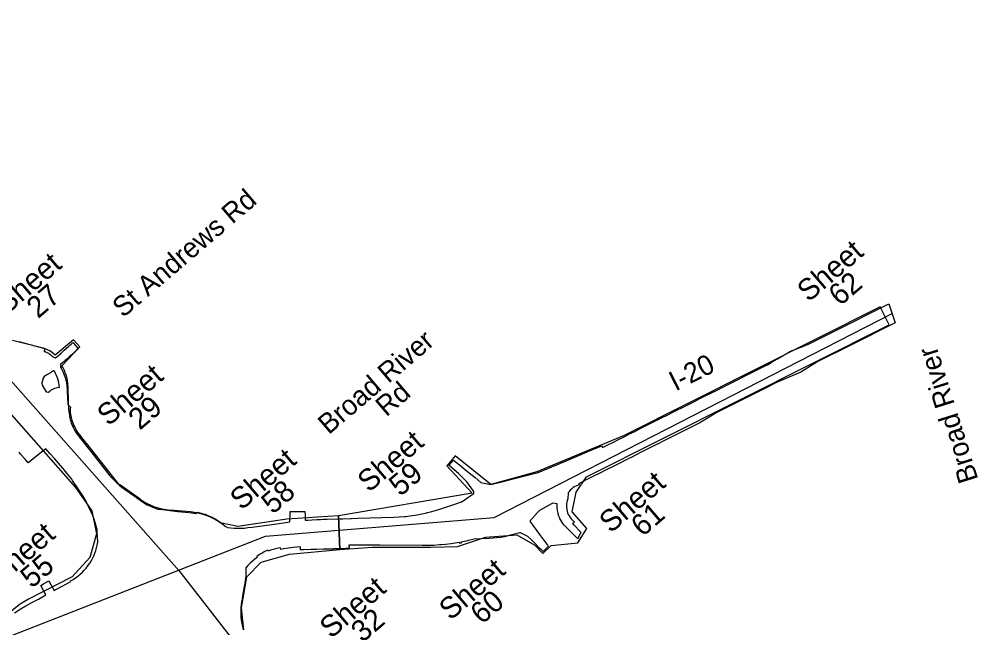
# Model space of a CAD drawing. Extents: x 1944182 to 1978751, y 789830 to 827717.
# Drawn here: x 1964336 to 1978751, y 800860 to 810005 of the extents above; entities that cross this region are included whole.
import ezdxf

# ---------------------------------------------------------------- set-up
doc = ezdxf.new("R2010")
doc.units = 0
for name, color, linetype in [('Default', 7, 'Continuous'), ('RD_AR_02', 7, 'Continuous'), ('RD_AR_03', 7, 'Continuous'), ('RD_SHT_ID', 7, 'Continuous'), ('RD_SHT_Misc4', 7, 'Continuous')]:
    doc.layers.add(name, color=color, linetype=linetype)

msp = doc.modelspace()

# ---------------------------------------------------------------- linework, layer by layer
at = {"layer": 'Default'}
for points in [[(1964332, 805162), (1964626, 805081), (1964700, 805061), (1964722, 805054), (1964721, 805051), (1964709, 805016), (1964709, 805016), (1964714, 805014), (1964716, 805014), (1964722, 805012), (1964724, 805011), (1964741, 805003), (1964749, 805000), (1964751, 804999), (1964766, 804991), (1964776, 804985), (1964788, 804978), (1964790, 804976), (1964799, 804970), (1964812, 804960), (1964821, 804953), (1964824, 804950), (1964833, 804942), (1964845, 804931), (1964880, 804914), (1964908, 804937), (1964920, 804948), (1964936, 804961), (1964966, 804989), (1965004, 805023), (1965012, 805030), (1965012, 805030), (1965077, 805089), (1965092, 805102), (1965117, 805124), (1965144, 805148), (1965151, 805139), (1965205, 805077), (1965205, 805077), (1965225, 805053), (1965200, 805030), (1965176, 805010), (1965175, 805009), (1965119, 804958), (1965093, 804935), (1965057, 804902), (1965026, 804874), (1965020, 804869), (1965013, 804863), (1965013, 804863), (1964989, 804842), (1964958, 804816), (1964958, 804813), (1964958, 804795), (1964958, 804778), (1964972, 804752), (1964978, 804740), (1964996, 804701), (1965002, 804687), (1965002, 804686), (1965012, 804661), (1965014, 804657), (1965014, 804655), (1965026, 804620), (1965031, 804600), (1965037, 804579), (1965040, 804565), (1965045, 804542), (1965045, 804537), (1965052, 804495), (1965052, 804488), (1965055, 804452), (1965057, 804416), (1965057, 804413), (1965069, 804227), (1965070, 804209), (1965105, 804177), (1965104, 804152), (1965103, 804105), (1965108, 804063), (1965117, 804022), (1965128, 803981), (1965141, 803941), (1965157, 803902), (1965166, 803885), (1965176, 803864), (1965196, 803827), (1965219, 803792), (1965244, 803758), (1965330, 803648), (1965343, 803632), (1965547, 803373), (1965843, 802998), (1965934, 802933), (1966065, 802842), (1966177, 802762), (1966259, 802710), (1966299, 802691), (1966340, 802673), (1966343, 802672), (1966382, 802658), (1966423, 802645), (1966450, 802641), (1966602, 802624), (1966721, 802610), (1966886, 802591), (1966931, 802585), (1966961, 802581), (1966992, 802576), (1967020, 802598), (1967088, 802578), (1967130, 802565), (1967172, 802549), (1967213, 802532), (1967252, 802512), (1967291, 802491), (1967329, 802467), (1967365, 802442), (1967400, 802415), (1967434, 802387), (1967468, 802367), (1967519, 802361), (1967570, 802357), (1967621, 802355), (1967672, 802356), (1967724, 802359), (1967775, 802365), (1967837, 802373), (1968211, 802424), (1968373, 802446), (1968408, 802450), (1968408, 802451), (1968410, 802561), (1968411, 802608), (1968633, 802610), (1968634, 802563), (1968634, 802562), (1968635, 802475), (1968683, 802478), (1968742, 802482), (1968819, 802487), (1968868, 802489), (1968909, 802490), (1968968, 802492), (1969154, 802498), (1969204, 802499), (1969330, 802503), (1969333, 802503), (1969429, 802506), (1969971, 802522), (1970050, 802525), (1970130, 802532), (1970149, 802534), (1970209, 802541), (1970288, 802552), (1970341, 802562), (1970342, 802562), (1970366, 802566), (1970444, 802583), (1970476, 802591), (1970522, 802602), (1970598, 802624), (1970674, 802648), (1970675, 802648), (1970888, 802720), (1970986, 802753), (1971026, 802779), (1971081, 802817), (1971083, 802818), (1971170, 802880), (1971172, 802907), (1971066, 803052), (1971022, 803096), (1970941, 803176), (1970877, 803233), (1970798, 803302), (1970805, 803310), (1970859, 803371), (1970868, 803381), (1970956, 803308), (1971057, 803225), (1971191, 803116), (1971279, 803043), (1971426, 803011), (1971591, 803054), (1971764, 803099), (1971785, 803104), (1972120, 803190), (1972141, 803196), (1972428, 803315), (1972724, 803439), (1972750, 803450), (1972840, 803487), (1972924, 803522), (1973012, 803559), (1973095, 803594), (1973109, 803570), (1973189, 803610), (1973270, 803651), (1973350, 803691), (1973431, 803731), (1973511, 803772), (1973592, 803812), (1973673, 803853), (1973753, 803893), (1973834, 803933), (1973914, 803974), (1973995, 804014), (1974088, 804061), (1974204, 804119), (1974328, 804181), (1974408, 804222), (1974489, 804262), (1974569, 804303), (1974650, 804343), (1974735, 804386), (1974829, 804433), (1974924, 804480), (1975035, 804536), (1975136, 804587), (1975251, 804645), (1975332, 804685), (1975412, 804725), (1975493, 804766), (1975581, 804810), (1975587, 804813), (1975659, 804855), (1975737, 804901), (1975835, 804957), (1975871, 804978), (1975934, 805015), (1976013, 805047), (1976118, 805089), (1976213, 805127), (1976576, 805309), (1977414, 805730), (1977507, 805441), (1977297, 805335), (1977061, 805217), (1976812, 805092), (1976347, 804859), (1976195, 804766), (1976091, 804702), (1975722, 804545), (1975566, 804467), (1974935, 804150), (1974935, 804150), (1974828, 804097), (1974571, 803940), (1974039, 803673), (1973945, 803626), (1973940, 803623), (1973689, 803498), (1973547, 803426), (1973501, 803403), (1973500, 803403), (1973498, 803402), (1973496, 803401), (1973475, 803390), (1973368, 803336), (1973255, 803280), (1973160, 803232), (1973056, 803180), (1972980, 803141), (1972980, 803141), (1972961, 803132), (1972931, 803117), (1972748, 803025), (1972757, 803008), (1972683, 802976), (1972662, 802962), (1972641, 802945), (1972622, 802927), (1972605, 802908), (1972599, 802900), (1972589, 802888), (1972586, 802799), (1972577, 802774), (1972571, 802748), (1972567, 802721), (1972566, 802706), (1972565, 802694), (1972566, 802668), (1972569, 802641), (1972574, 802615), (1972582, 802589), (1972582, 802588), (1972592, 802564), (1972605, 802540), (1972619, 802517), (1972635, 802496), (1972654, 802476), (1972679, 802450), (1972683, 802447), (1972675, 802439), (1972658, 802422), (1972665, 802415), (1972673, 802408), (1972674, 802407), (1972782, 802299), (1972760, 802254), (1972757, 802248), (1972735, 802198), (1972637, 802295), (1972622, 802311), (1972555, 802377), (1972533, 802400), (1972513, 802425), (1972495, 802451), (1972479, 802478), (1972467, 802502), (1972465, 802506), (1972452, 802536), (1972442, 802566), (1972438, 802585), (1972435, 802597), (1972429, 802628), (1972426, 802660), (1972425, 802692), (1972426, 802723), (1972360, 802735), (1972340, 802723), (1972158, 802623), (1972128, 802590), (1972013, 802463), (1972160, 802263), (1972219, 802182), (1972269, 802115), (1972278, 802102), (1972292, 802083), (1972283, 802075), (1972213, 802007), (1972188, 802032), (1972172, 802048), (1972064, 802156), (1972039, 802182), (1971986, 802234), (1971873, 802286), (1971866, 802289), (1971846, 802284), (1971746, 802256), (1971690, 802242), (1971633, 802229), (1971576, 802219), (1971519, 802211), (1971462, 802205), (1971404, 802201), (1971177, 802190), (1971092, 802170), (1971059, 802163), (1971006, 802152), (1970977, 802147), (1970980, 802132), (1970960, 802128), (1970957, 802143), (1970920, 802137), (1970833, 802124), (1970746, 802113), (1970687, 802108), (1970658, 802105), (1970571, 802099), (1970483, 802096), (1970395, 802096), (1969764, 802100), (1969756, 802101), (1969735, 802101), (1969435, 802103), (1969295, 802104), (1969297, 802056), (1969247, 802053), (1969145, 802049), (1969061, 802046), (1968959, 802041), (1968908, 802040), (1968807, 802038), (1968722, 802036), (1968617, 802034), (1968567, 802032), (1968565, 802079), (1968458, 802067), (1968423, 802062), (1968351, 802052), (1968311, 802045), (1968272, 802036), (1968266, 802064), (1968228, 802057), (1968190, 802048), (1968153, 802037), (1968116, 802025), (1968080, 802011), (1968074, 802025), (1968031, 802005), (1967989, 801983), (1967948, 801959), (1967908, 801933), (1967917, 801921), (1967879, 801893), (1967843, 801863), (1967808, 801830), (1967776, 801796), (1967745, 801761), (1967746, 801721), (1967746, 801680), (1967743, 801640), (1967739, 801600), (1967733, 801560), (1967695, 801340), (1967682, 801260), (1967679, 801244), (1967675, 801213), (1967670, 801165), (1967668, 801117), (1967668, 801069), (1967670, 801030), (1967671, 801020), (1967676, 800973), (1967683, 800925), (1967693, 800878), (1967705, 800831)], [(1964266, 801085), (1964351, 801138), (1964437, 801189), (1964525, 801238), (1964624, 801292), (1964624, 801292), (1964738, 801353), (1964660, 801498), (1964701, 801520), (1964783, 801564), (1964812, 801511), (1964861, 801420), (1964908, 801445), (1965114, 801557), (1965109, 801566), (1965146, 801588), (1965182, 801611), (1965217, 801637), (1965251, 801664), (1965283, 801693), (1965313, 801724), (1965341, 801756), (1965368, 801790), (1965393, 801826), (1965401, 801838), (1965416, 801862), (1965437, 801900), (1965456, 801939), (1965473, 801979), (1965487, 802019), (1965500, 802061), (1965510, 802102), (1965518, 802145), (1965510, 802295), (1965508, 802334), (1965507, 802337), (1965495, 802388), (1965479, 802442), (1965461, 802494), (1965442, 802547), (1965420, 802598), (1965380, 802682), (1965332, 802778), (1965325, 802791), (1965307, 802825), (1965138, 803073), (1965126, 803091), (1965051, 803185), (1964991, 803259), (1964929, 803333), (1964866, 803405), (1964802, 803476), (1964735, 803550), (1964716, 803535), (1964716, 803535), (1964470, 803340), (1964424, 803393), (1964358, 803468), (1964345, 803483), (1964330, 803497)]]:
    msp.add_lwpolyline(points, dxfattribs=at)
for points in [[(1964890, 804467), (1964910, 804471), (1964931, 804474), (1964944, 804471), (1964938, 804508), (1964931, 804544), (1964922, 804580), (1964910, 804615), (1964897, 804650), (1964882, 804683), (1964865, 804716), (1964851, 804719), (1964807, 804691), (1964761, 804664), (1964714, 804638), (1964694, 804613), (1964681, 804555), (1964678, 804539), (1964683, 804506), (1964743, 804407), (1964778, 804402), (1964795, 804417), (1964813, 804430), (1964832, 804442), (1964852, 804453), (1964871, 804461)], [(1968959, 802041), (1969061, 802045), (1968958, 802041)]]:
    msp.add_lwpolyline(points, close=True, dxfattribs=at)
at = {"layer": 'RD_AR_02'}
for p, q in [((1977284, 805681), (1973435, 803750)), ((1977419, 805413), (1977284, 805681)), ((1972865, 803128), (1977419, 805413)), ((1973435, 803750), (1972122, 803205)), ((1970893, 803442), (1970764, 803294)), ((1971430, 803013), (1970893, 803442)), ((1970764, 803294), (1971148, 802882)), ((1972122, 803205), (1971430, 803013)), ((1972710, 802898), (1972865, 803128)), ((1971148, 802882), (1969138, 802540)), ((1972653, 802601), (1972710, 802898)), ((1969138, 802540), (1969158, 802039)), ((1972871, 802354), (1972653, 802601)), ((1972734, 802137), (1972871, 802354)), ((1970927, 802081), (1971348, 802220)), ((1971348, 802220), (1971821, 802256)), ((1971821, 802256), (1972091, 802103)), ((1969158, 802039), (1969651, 802071)), ((1969651, 802071), (1970522, 802072)), ((1970522, 802072), (1970927, 802081)), ((1972091, 802103), (1972211, 801977)), ((1972211, 801977), (1972337, 802097)), ((1972337, 802097), (1972734, 802137))]:
    msp.add_line(p, q, dxfattribs=at)
at = {"layer": 'RD_AR_03'}
for p, q in [((1964698, 805062), (1964234, 805178)), ((1965153, 805189), (1964876, 804958)), ((1964978, 804796), (1965250, 805082)), ((1965250, 805082), (1965153, 805189)), ((1964700, 805062), (1964698, 805062)), ((1965083, 804137), (1965073, 804435)), ((1964181, 804107), (1965182, 802966)), ((1965242, 803730), (1965227, 803745)), ((1965437, 803482), (1965242, 803730)), ((1965706, 803141), (1965437, 803482)), ((1965182, 802966), (1965430, 802616)), ((1966156, 802791), (1965843, 803011)), ((1965430, 802616), (1965498, 802270)), ((1966911, 802602), (1966604, 802628)), ((1968362, 802492), (1967625, 802384)), ((1969138, 802540), (1968362, 802492)), ((1969158, 802039), (1969138, 802540)), ((1967625, 802384), (1967357, 802437)), ((1965498, 802270), (1965400, 801918)), ((1965400, 801918), (1965132, 801626)), ((1967974, 801847), (1968400, 801966)), ((1968400, 801966), (1969158, 802039)), ((1967761, 801628), (1967974, 801847)), ((1965132, 801626), (1964478, 801288)), ((1967680, 801162), (1967761, 801628)), ((1964351, 801214), (1963931, 800887)), ((1964478, 801288), (1964351, 801214)), ((1967713, 800827), (1967680, 801162))]:
    msp.add_line(p, q, dxfattribs=at)
for centre, radius, start, end in [((1964598, 804688), 387, 44.0266, 74.6235), ((1964279, 804391), 808, 16.848, 30.0467), ((1964273, 804441), 800, 359.526, 13.305), ((1965782, 804162), 699, 182.0585, 198.4561), ((1965778, 804179), 702, 199.8359, 218.2244), ((1966220, 803546), 654, 218.2244, 234.8554), ((1966681, 803538), 913, 234.8554, 265.175), ((1966836, 801714), 891, 54.2318, 85.175)]:
    msp.add_arc(centre, radius, start, end, dxfattribs=at)
at = {"layer": 'RD_SHT_Misc4'}
for p, q in [((1959396, 810005), (1966734, 801722)), ((1971476, 802516), (1977461, 805585)), ((1968039, 802236), (1971476, 802516)), ((1964119, 800706), (1968039, 802236)), ((1966734, 801722), (1971705, 795370))]:
    msp.add_line(p, q, dxfattribs=at)

# ---------------------------------------------------------------- texts
at = {"layer": 'RD_SHT_ID'}
for s, height, rotation, p in [('St Andrews Rd', 300, 40.5635, (1965898, 805509)), ('Sheet', 320, 40.5635, (1976206, 805744)), ('Sheet', 320, 40.5635, (1964149, 805558)), ('62', 320, 40.5635, (1976678, 805684)), ('27', 320, 40.5635, (1964620, 805497)), ('Broad River', 300, 40.5635, (1968990, 803753)), ('I-20', 300, 26.7313, (1974204, 804410)), ('Broad River', 300, 107.4392, (1978761, 803090)), ('Sheet', 320, 40.5635, (1965679, 803879)), ('Rd', 300, 40.5635, (1969856, 804021)), ('29', 320, 40.5635, (1966150, 803820)), ('Sheet', 320, 40.5635, (1969595, 802883)), ('Sheet', 320, 40.5635, (1967678, 802615)), ('59', 320, 40.5635, (1970067, 802823)), ('58', 320, 40.5635, (1968149, 802555)), ('Sheet', 320, 40.5635, (1973230, 802271)), ('61', 320, 40.5635, (1973708, 802217)), ('Sheet', 320, 40.5635, (1964052, 801500)), ('55', 320, 40.5635, (1964525, 801442)), ('Sheet', 320, 40.5635, (1970821, 800960)), ('Sheet', 320, 40.5635, (1969026, 800687)), ('60', 320, 40.5635, (1971292, 800900)), ('32', 320, 40.5635, (1969498, 800627))]:
    msp.add_text(s, height=height, rotation=rotation, dxfattribs=at).set_placement(p)

doc.saveas('drawing.dxf')
